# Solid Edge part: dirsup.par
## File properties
Author: there
Template: iso metric part.par
Last saved by: there
Revision: 3
Application: Solid Edge
Precisión: 0.990
Username: there
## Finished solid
Body 1: solid body, 10 faces, 20 edges, 10 vertices.
  Faces by surface: plane 6, cylinder 4
  Edges by curve: line 12, circle 4, ellipse 4
Bounding box of the edges (mm): 20.000 x 20.000 x 35.000, from (-10, -15, -15) to (10, 5, 20).
Cylindrical faces by radius (mm): R3.2 x4
Planar faces by outward normal: +x 1, +y 1, +z 1, -x 1, -y 1, -z 1
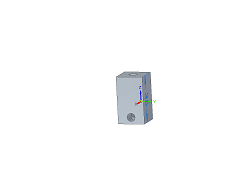
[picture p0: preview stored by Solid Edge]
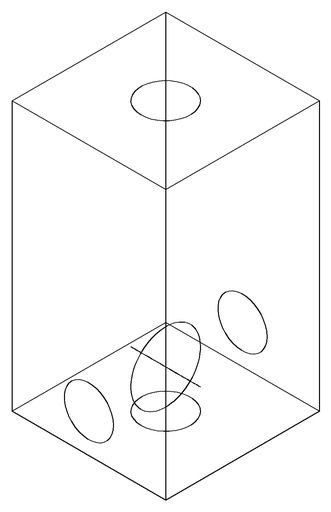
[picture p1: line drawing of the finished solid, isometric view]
